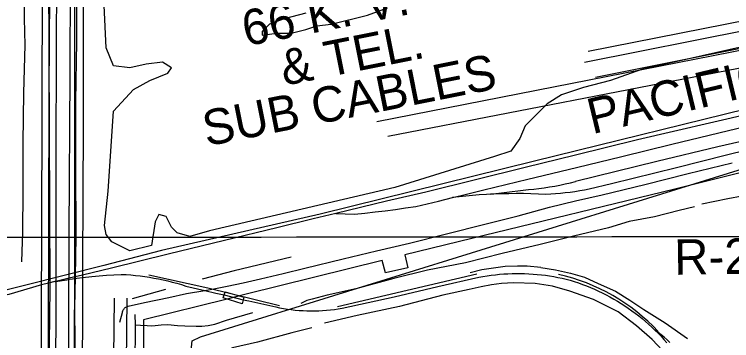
# Model space of a CAD drawing. Extents: x 3313447 to 3351316, y 703786 to 729172.
# Drawn here: x 3319138 to 3320817, y 721049 to 721813 of the extents above; entities that cross this region are included whole.
import ezdxf

# ---------------------------------------------------------------- set-up
doc = ezdxf.new("R2010")
doc.units = 0
for name, color, linetype in [('V-BRDG-OTLN', 7, 'Continuous'), ('V-DTCH-CNTR', 7, 'Continuous'), ('V-GRID-MAJR', 7, 'Continuous'), ('V-RAIL-IDEN', 7, 'Continuous'), ('V-RAIL-TRAK', 7, 'Continuous'), ('V-RIVR-RANG-IDEN', 7, 'Continuous'), ('V-ROAD-CNTR', 7, 'Continuous'), ('V-SITE-OTLN', 7, 'Continuous'), ('V-SITE-VEGE', 7, 'Continuous'), ('V-TOPO-SHOR', 7, 'Continuous'), ('V-UTIL-IDEN', 7, 'Continuous'), ('V-UTIL-LINE', 7, 'Continuous')]:
    doc.layers.add(name, color=color, linetype=linetype)

msp = doc.modelspace()

# ---------------------------------------------------------------- linework, layer by layer
at = {"layer": 'V-BRDG-OTLN'}
for points in [[(3319199.972, 720488.453), (3319200.704, 720769.949), (3319201.543, 721093.166), (3319203.3000000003, 721565.843), (3319204.214, 721917.58), (3319222.375, 721919.02), (3319236.437, 721920.136), (3319234.819, 721500.8), (3319234.844, 721103.642), (3319231.714, 720712.828), (3319231.639, 720488.371), (3319212.932, 720488.421)], [(3319264.575, 720509.318), (3319264.992, 720873.731), (3319266.637, 721303.103), (3319268.65, 721671.208), (3319269.764, 721897.25), (3319284.022, 721897.9890000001), (3319298.8170000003, 721898.757), (3319298.973, 721552.299), (3319297.592, 721224.859), (3319296.685, 720875.763), (3319296.636, 720653.4180000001), (3319295.2060000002, 720509.238), (3319279.59, 720509.279)], [(3319631.326, 721163.458), (3319675.213, 721150.535), (3319673.507, 721144.34), (3319671.055, 721135.447), (3319626.716, 721149.2880000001), (3319628.881, 721155.937)]]:
    msp.add_lwpolyline(points, close=True, dxfattribs=at)
for points in [[(3319212.932, 720488.421), (3319213.198, 720591.206), (3319214.3370000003, 720712.9), (3319217.255, 720886.394), (3319217.6180000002, 721026.182), (3319218.4620000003, 721350.162), (3319219.123, 721605.068), (3319220.397, 721779.39), (3319222.375, 721919.02)], [(3319279.59, 720509.279), (3319278.151, 720587.282), (3319279.486, 720784.627), (3319280.752, 720955.659), (3319279.552, 721126.698), (3319280.807, 721198.616), (3319282.449, 721292.7930000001), (3319282.062, 721459.7170000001), (3319281.63, 721610.196), (3319284.4590000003, 721749.155), (3319284.022, 721897.9890000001)]]:
    msp.add_lwpolyline(points, dxfattribs=at)
at = {"layer": 'V-DTCH-CNTR'}
for points in [[(3319583.6180000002, 721166.513), (3319608.5300000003, 721170.6630000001), (3319636.381, 721176.505), (3319673.286, 721184.0650000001), (3319714.3710000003, 721194.049), (3319767.293, 721206.091), (3319817.432, 721218.836), (3319907.612, 721240.522), (3319985.255, 721259.458), (3320062.897, 721277.003), (3320149.2490000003, 721299.0480000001), (3320238.734, 721321.78), (3320316.73, 721341.4130000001), (3320390.551, 721361.4010000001), (3320451.483, 721376.206), (3320513.455, 721390.311), (3320613.3850000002, 721414.758), (3320715.056, 721440.591), (3320817.772, 721465.376)], [(3319384.585, 721092.257), (3319390.907, 721114.859), (3319391.2970000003, 721116.743), (3319391.8910000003, 721118.572), (3319392.681, 721120.3250000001), (3319393.662, 721121.982), (3319394.815, 721123.52), (3319396.13, 721124.9230000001), (3319397.592, 721126.174), (3319399.181, 721127.255), (3319400.881, 721128.158), (3319402.669, 721128.8690000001), (3319404.523, 721129.379), (3319442.466, 721138.0380000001), (3319499.562, 721149.72), (3319540.647, 721159.356), (3319583.6180000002, 721166.513)]]:
    msp.add_lwpolyline(points, dxfattribs=at)
at = {"layer": 'V-GRID-MAJR'}
msp.add_spline([(3317583.083, 721289.311), (3322833.044, 721295.0380000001), (3328083.005, 721301.528), (3333332.965, 721308.783), (3338582.924, 721316.8), (3343832.882, 721325.582), (3349082.838, 721335.127), (3349082.839, 721335.127)], degree=3, dxfattribs=at)
at = {"layer": 'V-RAIL-TRAK'}
for p, q in [((3319232.994, 721187.128), (3319234.838, 721187.432)), ((3319266.223, 721195.112), (3319234.838, 721187.571)), ((3319628.881, 721155.937), (3319673.507, 721144.34))]:
    msp.add_line(p, q, dxfattribs=at)
for points in [[(3320859.455, 721580.5430000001), (3320596.289, 721518.909), (3320451.489, 721483.372), (3320333.6410000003, 721454.104), (3320101.117, 721396.6140000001), (3320009.17, 721375.729), (3319890.265, 721346.9890000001), (3319837.406, 721333.9720000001), (3319752.336, 721313.019), (3319629.735, 721283.763), (3319497.6210000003, 721251.3640000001), (3319365.504, 721218.963), (3319297.535, 721202.634), (3319266.223, 721195.112)], [(3319890.265, 721346.9890000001), (3319934.088, 721344.984), (3319958.0640000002, 721347.5260000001), (3319982.0160000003, 721350.274), (3320005.944, 721353.232), (3320029.847, 721356.394), (3320053.718, 721359.765), (3320077.563, 721363.34), (3320130.651, 721375.9500000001), (3320163.259, 721383.878), (3320183.674, 721388.84), (3320236.627, 721402.009), (3320339.678, 721427.091), (3320453.295, 721454.257), (3320559.517, 721480.388), (3320676.8340000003, 721509.129), (3320764.0300000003, 721530.027), (3320851.2260000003, 721551.453)], [(3320914.253, 721532.341), (3320784.256, 721502.576), (3320641.576, 721468.62), (3320451.327, 721421.581)], [(3320944.3200000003, 721518.003), (3320804.275, 721482.985), (3320687.484, 721453.713), (3320535.813, 721416.081), (3320483.497, 721403.5430000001), (3320472.305, 721401.372), (3320461.076, 721399.412), (3320449.809, 721397.661), (3320438.515, 721396.1190000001), (3320427.191, 721394.787), (3320415.845, 721393.669), (3320404.481, 721392.762), (3320393.102, 721392.068), (3320381.711, 721391.584), (3320364.3510000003, 721392.334), (3320346.9790000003, 721392.862), (3320329.6040000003, 721393.165), (3320312.227, 721393.247), (3320294.85, 721393.106), (3320277.474, 721392.7440000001), (3320260.107, 721392.158), (3320252.546, 721391.804), (3320242.7460000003, 721391.349), (3320225.4, 721390.317), (3320163.259, 721383.878)], [(3320252.546, 721391.804), (3320328.623, 721401.64), (3320341.0300000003, 721402.65), (3320353.418, 721403.881), (3320365.7800000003, 721405.329), (3320378.117, 721406.998), (3320390.4220000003, 721408.886), (3320402.6890000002, 721410.991), (3320414.918, 721413.314), (3320427.103, 721415.853), (3320439.242, 721418.612), (3320451.327, 721421.581)], [(3319280.731, 721194.354), (3319284.526, 721194.8740000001), (3319297.519, 721196.471)], [(3319297.519, 721196.471), (3319319.035, 721198.888), (3319336.326, 721200.549), (3319353.6380000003, 721201.983), (3319370.966, 721203.183), (3319388.311, 721204.153), (3319399.29, 721203.555), (3319410.255, 721202.7490000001), (3319421.204, 721201.731), (3319432.13, 721200.504), (3319443.029, 721199.066), (3319453.9020000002, 721197.422), (3319464.738, 721195.566), (3319475.535, 721193.506), (3319486.291, 721191.237), (3319496.998, 721188.763), (3319507.656, 721186.084), (3319518.258, 721183.2000000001), (3319528.801, 721180.1140000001), (3319539.2830000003, 721176.827), (3319583.6180000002, 721166.513)], [(3319673.507, 721144.34), (3319687.0670000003, 721142.115), (3319749.877, 721127.691), (3319758.884, 721125.867), (3319767.93, 721124.243), (3319777.011, 721122.8250000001), (3319786.12, 721121.613), (3319795.256, 721120.603), (3319804.413, 721119.8030000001), (3319813.5840000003, 721119.209), (3319822.765, 721118.822), (3319831.955, 721118.6410000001), (3319841.146, 721118.67), (3319850.333, 721118.903), (3319859.514, 721119.346), (3319868.681, 721119.993), (3319877.8340000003, 721120.8470000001), (3319886.9620000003, 721121.91), (3319896.065, 721123.176), (3319905.1380000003, 721124.648), (3320026.676, 721151.794), (3320129.1950000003, 721175.821), (3320224.843, 721197.225), (3320234.487, 721199.029), (3320244.164, 721200.633), (3320253.873, 721202.036), (3320263.611, 721203.236), (3320273.37, 721204.237), (3320283.149, 721205.034), (3320292.941, 721205.63), (3320302.745, 721206.025), (3320312.553, 721206.216), (3320322.364, 721206.204), (3320332.1720000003, 721205.9890000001), (3320341.974, 721205.573), (3320351.7660000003, 721204.952), (3320361.541, 721204.131), (3320371.2970000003, 721203.107), (3320381.031, 721201.88), (3320390.739, 721200.455), (3320400.414, 721198.829), (3320410.054, 721197.002), (3320419.653, 721194.976), (3320429.207, 721192.752), (3320438.715, 721190.334), (3320448.3680000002, 721187.323), (3320457.9560000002, 721184.112), (3320467.4760000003, 721180.702), (3320476.921, 721177.091), (3320486.288, 721173.286), (3320495.576, 721169.284), (3320504.776, 721165.09), (3320513.887, 721160.703), (3320522.9050000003, 721156.126), (3320531.824, 721151.362), (3320540.64, 721146.412), (3320549.353, 721141.28), (3320557.954, 721135.965), (3320566.4450000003, 721130.473), (3320574.8170000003, 721124.804), (3320583.071, 721118.959), (3320591.197, 721112.946), (3320599.199, 721106.761), (3320607.0670000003, 721100.41), (3320614.803, 721093.897), (3320622.399, 721087.225), (3320629.855, 721080.395), (3320637.165, 721073.407), (3320644.329, 721066.272), (3320651.341, 721058.985), (3320658.2, 721051.555), (3320664.901, 721043.984)], [(3319201.865, 721179.649), (3319125.048, 721157.269), (3319031.5160000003, 721136.387), (3318914.727, 721108.172), (3318818.018, 721084.128), (3318730.296, 721063.759)], [(3319234.838, 721187.571), (3319232.994, 721187.128), (3319217.987, 721183.524), (3319201.865, 721179.649)], [(3319234.838, 721187.432), (3319250.1380000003, 721189.938), (3319266.213, 721192.355)], [(3319266.213, 721192.355), (3319267.3170000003, 721192.5210000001), (3319280.731, 721194.354)], [(3319583.6180000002, 721166.513), (3319609.48, 721160.2710000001), (3319628.881, 721155.937)], [(3320672.29, 721044.817), (3320665.542, 721050.8690000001), (3320658.65, 721056.757), (3320651.6210000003, 721062.4770000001), (3320644.46, 721068.029), (3320637.165, 721073.407)]]:
    msp.add_lwpolyline(points, dxfattribs=at)
at = {"layer": 'V-ROAD-CNTR'}
for points in [[(3319275.447411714, 715676.808619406), (3319267.433427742, 716170.3776322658), (3319268.956424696, 717056.7608594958), (3319273.120416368, 717958.7330555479), (3319277.765407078, 718937.6720976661), (3319279.2634040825, 719832.981307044), (3319276.1484103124, 720458.726055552), (3319279.42440376, 721216.0285409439), (3319279.533403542, 721926.3111203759), (3319286.4993896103, 722373.937225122), (3319288.966384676, 723220.472532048), (3319295.263372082, 724050.666871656), (3319298.091366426, 724572.1338287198)], [(3319225.7395111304, 724387.15419868), (3319219.8795228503, 723260.4824520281), (3319216.86452888, 722088.9557950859), (3319220.7045212, 721173.5236259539), (3319213.4595356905, 720516.397940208), (3319203.015556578, 719335.8683012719), (3319201.881558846, 718251.3094703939), (3319197.952566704, 717354.6582637), (3319193.2855760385, 716367.9212371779), (3319200.9165607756, 715645.185682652)], [(3321599.017764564, 721774.9144231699), (3321486.4609896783, 721744.793483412), (3321382.659197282, 721724.407524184), (3321193.099576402, 721673.40962618), (3320900.4761616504, 721603.2987664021), (3320354.97225266, 721469.442034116), (3319853.704255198, 721345.2962824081), (3319482.2569980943, 721260.223452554), (3319347.642267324, 721225.1355227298), (3319071.498819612, 721155.4696620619), (3318801.6813592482, 721085.8358013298), (3318597.173768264, 721038.4098961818), (3318497.648967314, 721012.8879472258), (3318053.893854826, 720830.5203119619), (3317615.848730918, 720718.779535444), (3317581.334799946, 720710.5405519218)], [(3319758.149446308, 721130.7837114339), (3319590.492781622, 721171.7506294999), (3319452.9920566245, 721201.969569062)], [(3320220.340521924, 721204.524563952), (3319894.204174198, 721127.7377175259)], [(3319368.6711772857, 720803.7963803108), (3319372.156218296, 721148.4796760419)], [(3319391.045180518, 720402.7171675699), (3319395.995170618, 720539.032894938), (3319402.1541583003, 721148.1756766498)]]:
    msp.add_lwpolyline(points, dxfattribs=at)
msp.add_arc((3320314.941103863, 720764.668979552), 449.4240251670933, 42.82443558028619, 77.59976335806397, dxfattribs=at)
at = {"layer": 'V-SITE-OTLN'}
msp.add_lwpolyline([(3322017.001, 719673.736), (3320119.971, 719808.487), (3319440.938, 719820.238), (3319430.9790000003, 719830.251), (3319553.977, 721048.247), (3319573.9760000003, 721058.182), (3321043.134, 721513.729), (3321922.666, 721801.0430000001), (3321982.5840000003, 721800.887), (3322002.452, 721760.892), (3322097.018, 719723.46)], close=True, dxfattribs=at)
at = {"layer": 'V-SITE-VEGE'}
for points in [[(3320983.346, 721768.9450000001), (3320605.5, 721683.979), (3320533.327, 721658.49), (3320469.646, 721641.498), (3320418.698, 721624.505), (3320384.734, 721603.264), (3320333.79, 721552.287), (3320321.054, 721522.55), (3320299.826, 721492.811), (3320261.619, 721480.066), (3320028.116, 721407.848), (3319595.079, 721305.892), (3319548.378, 721293.145), (3319518.66, 721301.642), (3319505.923, 721314.387), (3319493.187, 721339.877), (3319476.205, 721344.1240000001), (3319467.716, 721327.132), (3319459.225, 721271.905), (3319408.279, 721259.161), (3319365.824, 721280.4010000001), (3319353.0870000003, 721297.395), (3319348.842, 721318.635), (3319357.333, 721399.35), (3319370.069, 721586.273), (3319416.772, 721637.25), (3319454.977, 721658.49), (3319497.432, 721675.484), (3319505.923, 721688.229), (3319484.696, 721700.974), (3319446.486, 721696.724), (3319408.279, 721688.229), (3319370.069, 721692.4770000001), (3319353.0870000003, 721734.958), (3319344.596, 721917.632)], [(3319820.088, 721815.674), (3319769.142, 721802.929), (3319735.178, 721790.183), (3319718.198, 721773.192), (3319718.198, 721764.6950000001), (3319752.16, 721768.9450000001), (3319786.1240000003, 721768.9450000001), (3319820.088, 721777.4400000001), (3319845.561, 721785.937), (3319879.5270000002, 721790.183), (3319964.433, 721811.426), (3320011.134, 721828.419)]]:
    msp.add_lwpolyline(points, dxfattribs=at)
at = {"layer": 'V-TOPO-SHOR'}
msp.add_line((3319492.0810000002, 721168.631), (3319413.517, 721147.0700000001), dxfattribs=at)
for points in [[(3319155.512, 721233.27), (3319157.7630000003, 721304.495), (3319158.349, 721397.405), (3319158.648, 721512.339), (3319159.983, 721628.9890000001), (3319163.0270000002, 721741.162), (3319161.468, 721803.105), (3319160.966, 721875.027), (3319164.259, 721950.723), (3319162.713, 722017.14), (3319155.068, 722120.738), (3319148.383, 722197.493), (3319144.414, 722259.443), (3319133.558, 722318.659), (3319123.066, 722386.134), (3319109.801, 722445.7000000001), (3319097.884, 722494.938), (3319083.568, 722547.281), (3319064.45, 722605.829), (3319058.992, 722624.769), (3319057.628, 722629.936)], [(3321357.69, 721053.2000000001), (3321294.116, 721055.532), (3321216.818, 721058.26), (3321141.329, 721062.43), (3321075.947, 721064.046), (3321037.657, 721064.867), (3321028.63, 721065.975), (3321023.938, 721067.794), (3321020.3370000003, 721072.137), (3321018.916, 721081.1730000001), (3321019.348, 721108.264), (3321021.998, 721155.581), (3321022.154, 721215.547), (3321025.269, 721301.515), (3321025.34, 721329.692), (3321024.6520000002, 721343.059), (3321018.889, 721349.215), (3320999.038, 721355.409), (3320940.1890000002, 721368.927), (3320875.927, 721383.904), (3320857.5130000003, 721387.566), (3320841.616, 721387.245), (3320808.005, 721380.83), (3320746.612, 721368.524)], [(3320729.857, 721362.482), (3320693.782, 721353.672), (3320635.944, 721338.65), (3320576.671, 721327.607), (3320528.588, 721312.921), (3320446.897, 721293.987), (3320368.8170000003, 721273.96), (3320279.535, 721253.24), (3320193.863, 721231.066), (3320104.953, 721213.957), (3320025.79, 721194.655), (3319937.222, 721170.321), (3319869.992, 721155.323), (3319834.928, 721146.384), (3319822.274, 721142.804), (3319808.595, 721135.99)], [(3319786.128, 721244.487), (3319652.398, 721212.329), (3319577.179, 721192.5)], [(3320369.761, 721220.4940000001), (3320338.214, 721222.979), (3320315.541, 721223.648), (3320286.8910000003, 721222.868), (3320264.9390000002, 721219.634), (3320232.375, 721214.355), (3320205.053, 721208.088)], [(3320369.761, 721220.4940000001), (3320404.063, 721214.985), (3320439.4450000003, 721206.584), (3320471.934, 721197.831), (3320504.407, 721182.936), (3320544.458, 721164.408), (3320578.721, 721143.367), (3320610.815, 721121.969), (3320660.948, 721090.772), (3320713.076, 721053.607)], [(3320654.65, 721025.533), (3320630.72, 721051.34), (3320593.714, 721083.725), (3320551.038, 721116.563), (3320493.08, 721145.073), (3320438.15, 721164.416), (3320397.602, 721176.3030000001), (3320356.603, 721182.953), (3320306.1750000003, 721184.296), (3320278.132, 721182.4180000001), (3320254.84, 721179.5530000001), (3320230.446, 721175.228), (3320202.538, 721168.518), (3320140.981, 721155.589), (3320039.245, 721128.799), (3319940.14, 721107.676), (3319864.028, 721090.0530000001)], [(3319420.38, 721085.537), (3319433.059, 721085.503), (3319449.148, 721083.9990000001), (3319458.412, 721083.61), (3319467.556, 721084.196), (3319481.458, 721085.865), (3319496.8200000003, 721086.68), (3319520.099, 721084.302), (3319537.163, 721083.5260000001), (3319563.251, 721082.85), (3319576.661, 721083.059), (3319591.538, 721084.606), (3319607.27, 721087.612), (3319634.603, 721097.17), (3319696.3340000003, 721114.809)], [(3319419.921, 721110.453), (3319420.38, 721085.537), (3319419.606, 720989.0750000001), (3319420.7, 720859.686), (3319419.373, 720823.279), (3319416.3910000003, 720807.358), (3319415.004, 720801.189), (3319411.5470000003, 720790.912)], [(3319834.324, 721078.718), (3319787.753, 721067.495), (3319706.973, 721045.4500000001), (3319648.47, 721032.076), (3319613.085, 721016.022), (3319589.895, 720991.647), (3319575.879, 720971.177), (3319571.037, 720955.045), (3319567.42, 720907.056), (3319560.13, 720787.519), (3319551.931, 720655.328), (3319545.347, 720553.701)]]:
    msp.add_lwpolyline(points, dxfattribs=at)
at = {"layer": 'V-UTIL-LINE'}
for p, q in [((3319986.044, 721562.216), (3327138.821, 722968.4670000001)), ((3320012.086, 721527.4940000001), (3327138.821, 722916.384)), ((3320480.835, 721727.147), (3326505.1410000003, 722916.384)), ((3320472.1550000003, 721701.105), (3326453.059, 722890.3420000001)), ((3320498.198, 721666.383), (3326435.696, 722855.62)), ((3319664.895, 721153.572), (3319635.998, 721146.392))]:
    msp.add_line(p, q, dxfattribs=at)
for points in [[(3321199.031, 721529.269), (3321044.284, 721491.011), (3321049.044, 721463.209), (3320999.4760000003, 721451.257), (3320989.8880000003, 721480.277), (3320684.017, 721403.75), (3320208.895, 721287.79), (3320051.732, 721249.535), (3320058.9020000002, 721219.313), (3320006.919, 721207.365), (3319998.537, 721236.383), (3319680.579, 721157.469), (3319664.895, 721153.572)], [(3319635.998, 721146.392), (3319439.994, 721097.684), (3319437.704, 720682.073)]]:
    msp.add_lwpolyline(points, dxfattribs=at)

# ---------------------------------------------------------------- texts
at = {"layer": 'V-RAIL-IDEN'}
msp.add_text('PACIFIC', height=82.999832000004, rotation=13.512472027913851, dxfattribs=at).set_placement((3320490.43198174, 721532.2262345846))
at = {"layer": 'V-RIVR-RANG-IDEN'}
msp.add_text('R-231.4', height=82.99999800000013, rotation=0.9353583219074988, dxfattribs=at).set_placement((3320682.818329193, 721202.8452714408))
at = {"layer": 'V-UTIL-IDEN'}
for s, height, rotation, p in [('66 K. V.', 82.99983199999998, 11.085253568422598, (3319679.8940597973, 721738.2430534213)), ('& TEL.', 82.99983200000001, 11.281425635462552, (3319769.3771396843, 721645.7034263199)), ('SUB CABLES', 82.99983200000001, 11.281425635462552, (3319587.770353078, 721503.7900748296))]:
    msp.add_text(s, height=height, rotation=rotation, dxfattribs=at).set_placement(p)

doc.saveas('drawing.dxf')
